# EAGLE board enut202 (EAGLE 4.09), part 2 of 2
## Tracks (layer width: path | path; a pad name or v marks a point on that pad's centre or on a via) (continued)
PD5  (via drill 0.4) (continued)
  Bottom 0.152: J5.60 14,72.18 14.05,72.13 12.3,70.38 12.3,62.07 13.06,61.31 17.56,61.31 v18.85,60.02 | v22.13,48.13 22.13,48.28 26.7,48.28 27.46,47.52 27.46,35.48 28.07,34.79 28.07,24.35 JP2.1
PD6  (via drill 0.4)
  Top 0.152: IC1.31 v18.03,59.57
  Bottom 0.152: J5.61 11.46,74.88 11.54,74.8 11.54,73.5 11.69,73.35 11.99,73.35 12.45,72.89 12.45,71.83 11.99,71.37 11.99,61.92 12.91,61.01 17.18,61.01 18.01,60.17 18.01,59.63 18.03,59.62 v18.03,59.57
PD7  (via drill 0.4)
  Top 0.152: IC1.32 v17.23,59.97
  Bottom 0.152: J5.62 11.69,72.13 11.69,61.77 12.75,60.7 16.57,60.7 17.25,60.02 17.25,59.94 v17.23,59.97
PE0  (via drill 0.4)
  Top 0.152: IC1.2 | IC1.2 | 31.2,48.36 31.21,48.37 IC1.2 | v38.36,70.07 38.36,73.86 J5.39 39.4,74.92 40.19,73.81 60.69,73.81 61.07,73.43 61.07,67.79 JP1.12 | v37.98,53.16 37.98,52.09 36.23,50.34 34.78,50.34 | IC1.2 31.25,48.36 32.26,48.36 32.34,48.28 32.72,48.28 34.78,50.34 | JP4.1C 18.32,23.13 19,22.45 22.66,22.45 24.19,23.97 24.19,29.46 27.77,29.46 29.67,31.36 29.67,32.74 30.36,33.42 v30.36,40.28 | 34.78,50.34 34.47,50.03 34.47,43.94 32.57,42.03 v32.03,42.03
  Bottom 0.152: v38.36,70.07 34.7,70.07 34.4,69.77 34.4,58.11 37.98,54.53 v37.98,53.16 | v30.36,40.28 v32.03,42.03
PE1  (via drill 0.4)
  Top 0.152: 31.23,49.16 31.2,49.12 | 31.23,49.16 IC1.3 | 31.23,49.16 31.25,49.17 31.25,49.27 31.32,49.2 32.95,49.2 34.4,50.64 36,50.64 37.37,52.02 v37.37,52.4 37.37,54.07 42.25,54.07 43.01,53.31 46.21,53.31 46.97,52.55 47.66,52.55 49.03,53.92 61.3,53.92 61.9,54.53 61.9,55.14 61.3,55.75 61.3,57.2 61.29,57.2 JP1.2 | JP4.9C 17.65,39.29 14.96,39.29 12.68,41.57 12.68,46.3 11.76,47.21 11.76,62.07 13.21,63.52 13.21,70.07 14.43,71.29 19.84,71.29 20.38,71.83 20.38,73.05 20.91,73.58 27.23,73.58 27.92,74.27 v27.92,75.48
  Bottom 0.152: v37.37,52.4 37.37,54.68 34.09,57.96 34.09,70 34.47,70.38 37.44,70.38 39.43,72.36 J5.40 39.04,73.05 38.36,73.73 38.36,74.88 37.29,75.94 28.38,75.94 v27.92,75.48
PE2  (via drill 0.4)
  Top 0.152: J5.41 36.84,74.8 36.84,74.88 38.59,76.02 62.82,76.02 63.28,75.56 63.28,69.08 v62.29,68.09 | IC1.4 31.23,49.96 32.95,49.96 33.94,50.95 35.69,50.95 36.76,52.02 v36.76,53.16
  Bottom 0.152: v36.76,53.16 36.76,54.83 33.79,57.81 33.79,70.23 34.24,70.68 36.76,70.68 38.13,72.05 38.13,73.12 36.86,74.39 J5.41 | v62.29,68.09 62.29,62.23 JP1.6
PE3  (via drill 0.4)
  Top 0.152: IC1.5 | IC1.5 | IC1.5 31.23,50.72 31.39,50.87 32.95,50.87 33.33,51.25 35.31,51.25 36.15,52.09 v36.15,52.4 | J5.42 36.86,72.87 35.69,74.04 35.69,75.33 36.68,76.32 63.28,76.32 63.73,75.86 63.73,68.17 64.11,67.79 64.11,66.8 63.66,66.34 62.36,66.34 62.36,64.82 61.68,64.13 61.68,64.05 | 61.68,64.05 59.47,64.05 59.24,64.28 R30.1 | 61.68,64.05 62.36,63.37 62.36,61.77 63.05,61.77 JP1.5
  Bottom 0.152: v36.15,52.4 36.15,54.99 33.48,57.65 33.48,70.45 34.02,70.99 35.54,70.99 36.86,72.31 J5.42
PE4  (via drill 0.4)
  Top 0.152: IC1.6 | IC1.6 | IC1.6 31.33,51.48 31.4,51.56 35.01,51.56 35.54,52.09 v35.54,53.16
  Bottom 0.152: v35.54,53.16 35.54,55.14 33.18,57.5 33.18,70.68 33.79,71.29 34.85,71.29 35.62,72.05 35.62,72.82 34.32,74.11 J5.43
PE5  (via drill 0.4)
  Top 0.152: IC1.7 | IC1.7 | IC2.29 47.61,23.74 v45.75,23.74 45.45,23.9 36,23.9 34.62,25.27 33.63,25.27 33.25,25.65 33.25,29.54 34.4,30.68 34.4,35.63 v35.01,36.24 | 31.23,52.36 31.27,52.32 | 31.23,52.36 IC1.7 | 31.23,52.36 31.2,52.4 29.75,52.4 29.75,47.37 30.28,46.83 30.28,45.61 v31.42,44.47 | IC1.7 31.26,52.4 v34.93,52.4
  Bottom 0.152: J5.44 32.87,70.91 32.87,57.35 34.93,55.29 v34.93,52.4 | v35.01,36.24 35.01,40.89 v31.42,44.47
PE6  (via drill 0.4)
  Top 0.152: IC1.8 | IC1.8 | v34.32,53.17 34.32,53.16 31.25,53.16 IC1.8
  Bottom 0.152: v34.32,53.17 34.32,53.08 34.32,55.44 32.57,57.2 32.57,71.37 33.02,71.83 33.02,72.82 31.78,74.06 J5.45
PE7  (via drill 0.4)
  Top 0.152: IC1.9 32.11,53.84 33.41,53.84 v33.44,53.82 | IC1.9 | J5.46 31.78,72.31 33.1,70.99 36.3,70.99 37.83,69.46 38.74,69.46 40.49,71.22 40.57,71.22 40.57,72.82 41.18,73.43 57.94,73.43 58.55,72.82 58.55,67.86 58.7,67.71 R31.1 58.7,66.8 58.17,66.8 58.17,64.13 58.78,63.37 60.69,63.37 JP1.8
  Bottom 0.152: v33.44,53.82 33.61,53.97 33.63,54 33.63,55.6 32.26,56.97 32.26,71.88 J5.46
PEN\
  Top 0.152: 33.39,47.52 33.41,47.52 | 33.39,47.52 R4.1 | IC1.1 31.29,47.52 33.39,47.52
PF0  (via drill 0.4)
  Top 0.152: IC1.61 v26.83,47.17
  Bottom 0.152: 26.59,46.95 24.49,44.85 20.22,44.85 | 26.59,46.95 26.85,47.21 | 20.22,44.85 20.25,44.85 | v26.83,47.17 26.62,46.91 26.59,46.95 | J6.5 8.11,49.5 8.26,49.35 8.26,45.84 9.25,44.85 20.22,44.85
PF1  (via drill 0.4)
  Top 0.152: IC1.60 | IC1.60 | IC1.60 26.01,45.59 v26.01,47.67
  Bottom 0.152: 26.03,47.57 26.01,47.29 v26.01,47.67 25.86,47.37 25.86,46.83 24.11,45.16 9.48,45.16 8.56,46.07 8.56,51.63 8.16,52.04 J6.7
PF2  (via drill 0.4)
  Top 0.152: IC1.59 25.23,45.67 v25.23,47.21
  Bottom 0.152: 25.02,46.98 23.5,45.46 9.78,45.46 8.87,46.38 8.87,53.92 8.21,54.58 J6.9 | 25.02,46.98 25.25,47.21 | 25.02,46.98 v25.23,47.21
PF3  (via drill 0.4)
  Top 0.152: IC1.58 24.43,45.67 v24.43,47.61
  Bottom 0.152: 20.22,45.77 20.23,45.77 | 20.22,45.77 23.2,45.77 24.41,46.98 24.41,47.59 v24.43,47.61 | J6.11 8.18,57.12 9.17,56.13 9.17,46.68 10.09,45.77 20.22,45.77
PF4  (via drill 0.4)
  Top 0.152: 23.63,45.47 | 23.63,45.47 IC1.57 23.65,45.59 23.65,47.21 | 23.65,47.21 23.65,47.19 v23.63,47.17 | IC3.11 41.49,57.97 41.41,57.88 40.65,57.88 39.81,57.04 39.81,55.29 39.04,54.53 v32.8,54.53 | 23.63,45.47 23.65,45.46 v23.65,43.02 | 23.65,47.21 23.65,47.98 24.03,48.36 26.78,48.36 27.23,48.81 v27.23,53.92
  Bottom 0.152: 23.39,46.95 22.51,46.07 10.39,46.07 9.48,46.98 9.48,58.34 8.16,59.66 J6.13 | 23.39,46.95 23.65,47.21 | v23.63,47.17 23.42,46.91 23.39,46.95 | v27.23,53.92 27.54,53.62 31.88,53.62 v32.8,54.53 | JP4.1A 22.59,24.45 22.59,31.67 22.89,31.97 22.89,42.57 v23.65,43.02
PF5  (via drill 0.4)
  Top 0.152: IC3.10 41.5,58.8 40.72,58.8 39.43,57.5 39.43,55.82 39.04,55.44 v32.8,55.44 | v22.89,43.71 22.89,45.52 IC1.56 22.83,45.67 v22.83,47.57 v22.83,47.58 22.81,47.59 22.89,47.67 22.89,47.9 23.8,48.81 25.94,48.81 26.47,49.35 v26.47,54.76
  Bottom 0.152: 22.81,47.29 22.81,47.59 | 22.81,47.29 22.81,47.06 22.13,46.38 10.7,46.38 9.78,47.29 9.78,60.55 8.13,62.2 J6.15 | v22.83,47.57 22.81,47.29 | v26.47,54.76 27.77,54.76 28.61,53.92 31.27,53.92 v32.8,55.44 | v22.89,43.71 22.59,43.71 22.59,32.28 21.75,31.44 21.75,31.36 21.72,31.36 JP4.5A
PF6  (via drill 0.4)
  Top 0.152: v22.03,47.13 IC1.55 22.13,44.62 22.13,43.1 22.89,42.34 24.72,42.34 v26.09,40.97
  Bottom 0.152: 22.05,47.13 22.05,47.14 | 22.05,47.13 v22.03,47.13 | 22.05,47.13 21.6,46.68 11,46.68 10.09,47.59 10.09,62.76 8.11,64.74 J6.17 | JP5.5 27.07,39.99 v26.09,40.97
PF7  (via drill 0.4)
  Top 0.152: IC1.54 | IC1.54 21.23,43.38 v23.5,41.12 | IC1.54 v21.23,47.61
  Bottom 0.152: v21.23,47.61 21.23,47.53 20.68,46.98 11.23,46.98 10.39,47.82 10.39,63.27 J6.19 | v23.5,41.12 23.2,40.81 23.2,31.97 24.81,30.36 JP5.2
POE+
  Bottom 0.61: J1.8 81.95,19.63 | JP3.3 81.95,20.65 J1.8 | J1.7 84.46,18.38 84.46,19.65 J1.8
POE-
  Bottom 0.61: JP3.2 75.23,17.04 80.04,17.04 80.04,14.6 81.95,14.6 J1.4 81.95,15.82 84.48,15.82 J1.5
RAMSEL\  (via drill 0.4)
  Top 0.152: v47.58,44.47 47.58,41.57 49.18,39.98 52.68,39.98 | 52.68,39.98 | 52.68,39.98 IC4.22 | IC3.6 41.58,61.92 43.31,61.92 43.92,62.53 v48.19,62.53
  Bottom 0.152: v47.58,44.47 49.18,46.15 49.18,50.49 48.49,51.18 48.49,51.79 49.41,52.7 49.41,56.21 49.71,56.51 49.71,61.69 48.87,62.53 v48.19,62.53
RD\  (via drill 0.4)
  Top 0.152: v46.28,24.58 46.89,24.58 IC2.31 | v51.24,28.62 51.24,31.82 53.06,31.82 53.83,32.58 53.83,42.26 53.45,42.26 IC4.24 53.45,42.79 v54.74,42.79 | IC1.34 15.21,58.8 v12.83,58.8 | IC3.3 42.47,64.37 43.16,63.67 48.04,63.67 48.95,62.76 48.95,61.16 48.57,60.78 48.42,60.78 48.19,60.55 48.19,59.94 48.65,59.48 49.33,59.48 51.47,57.35 52,57.35 54.82,54.53 v59.77,54.53
  Supply 0.305: J5.13 72.42,75.26 71.35,76.32 10.85,76.32 10.24,75.71 v10.24,73.81
  Bottom 0.152: v46.28,24.58 46.28,24.66 50.25,28.62 v51.24,28.62 | v10.24,73.81 10.24,71.83 11.38,70.68 11.38,60.24 v12.83,58.8 | v54.74,42.79 55.2,43.25 55.2,53 56.72,54.53 v59.77,54.53 60.69,55.44 62.21,55.44 62.67,54.99 67.54,54.99 68.23,55.67 68.23,63.98 73.94,69.69 73.94,72.97 72.42,74.49 J5.13
RDYRTN\  (via drill 0.4)
  Top 0.152: IC2.46 | IC2.46 | RN1.5 42.32,28.94 v42.32,28.24 | IC2.46 41.03,26.48 41.03,26.49 v41.03,24.73
  Bottom 0.152: v42.32,28.24 42.32,26.03 v41.03,24.73
RE485\
  Top 0.152: IC7.2 27.01,14.6 28.07,14.6 28.68,15.21 28.68,17.04 27.77,17.95 27.77,20.92 26.09,22.6 26.09,24.39 JP2.3 26.85,25.95 26.85,26.79 JP2.5
RESET  (via drill 0.4)
  Top 0.152: IC6.1 67.3,56.13 v64.65,56.13 | 37.52,32.67 37.52,32.66 | IC5.8 37.52,32.67 | 37.52,32.67 37.52,32.74 52.46,32.74 v52.76,32.43 | v59.92,57.04 59.92,61.08 59.24,61.77 R29.1
  Bottom 0.152: v64.65,56.13 64.57,56.28 59.92,56.28 | 59.92,56.28 v59.92,57.04 | 59.92,56.28 57.26,56.28 53.68,52.7 53.68,33.35 v52.76,32.43
RESET\  (via drill 0.4)
  Top 0.152: IC5.9 37.48,33.95 v35.23,33.95 | 67.39,65.74 IC6.18 67.34,65.81 | R2.1 31.12,66.43 31.12,65.58 | 31.12,65.58 D1.A | 31.12,65.58 28.91,63.37 28.22,63.37 27.77,62.91 27.46,62.91 26.83,62.28 IC1.20 26.85,61.56 v26.85,59.86 28.68,58.03 28.68,47.29 v28.61,47.21 | v28.99,34.26 28.07,33.42 21.78,33.42 JP4.6A 21.22,33.35 20.15,32.28 18.62,32.28 17.71,31.36 JP4.5C | J5.9 77.4,74.9 76.31,73.81 76.31,71.75 75.7,71.14 68.76,71.14 68.42,70.8 C22.1 67.97,69.82 66.48,68.32 66.48,65.81 67.34,65.81 | S1.2 18.16,8.2 v20.15,8.2 27.62,8.2 S1.1 | 67.34,65.81 67.39,65.81
  Bottom 0.152: v26.85,59.86 26.09,59.86 25.63,59.41 24.19,59.41 20.38,63.14 14.28,63.14 14.13,63.29 14.13,68.63 15.35,69.84 18.7,69.84 20.38,71.52 20.38,76.47 20.53,76.63 48.8,76.63 49.41,75.94 72.95,75.94 73.49,75.41 73.49,74.65 74.4,73.73 76.38,73.73 77.53,74.88 J5.9 | v35.23,33.95 29.29,33.95 v28.99,34.26 28.99,35.17 28.61,35.55 v28.61,47.21 | JP4.6A 20.76,32.4 20.76,21.61 20.15,21 v20.15,8.2
RO  (via drill 0.4)
  Top 0.152: IC7.1 27.01,13.31 v27.01,12.47
  Bottom 0.152: JP1.10 59.09,63.02 59.09,59.71 52.76,53.39 52.76,39.37 51.24,37.84 51.24,32.51 46.44,27.71 46.44,26.49 44.38,24.43 44.38,13.61 43.23,12.47 v27.01,12.47
RRCUP
  Top 0.152: R13.2 54.82,17.95 54.82,16.28 R12.2 54.82,15.36 54.82,12.54 C13.2
RS485A
  Top 0.152: J4.2 | JP6.6 10.62,15.21 J4.2 | IC7.6 22.05,16.12 22.31,16.38 22.31,19.07 21.26,19.07 20.4,19.93 20.35,19.97 12.57,19.97 11.3,18.7 11.28,18.64 JP6.10
  Bottom 0.152: JP6.6 10.19,15.64 10.19,17.11 11.3,18.23 11.3,18.54 11.29,18.54 JP6.10
RS485B
  Top 0.152: IC7.7 20.51,14.58 R24.1 19.08,15.85 17.81,17.11 15.27,17.11 14.63,16.48 14.63,16 14.16,15.53 12.25,15.53 11.25,16.53 JP6.8 10.08,17.75 J4.1 | J4.1
RSHIELD  (via drill 0.4)
  Top 0.152: J3.G1 88.44,66.33 83.85,66.33 C25.2 83.72,66.33 v82.58,66.33 81.31,66.33 C24.2 | C27.2 83.85,56.8 v82.58,56.8 81.44,56.8 C26.2
  Bottom 0.152: J3.G1 90.2,64.56 90.2,59.66 91.47,58.39 91.47,43.47 88.93,40.93 88.91,40.86 J3.G2 | v82.58,66.33 v82.58,56.8
  Bottom 0.61: J3.G2 87.66,42.06 R32.2
RXD  (via drill 0.4)
  Top 0.152: v64.11,64.21 72.72,64.21 73.41,64.89 IC6.13
  Bottom 0.152: v64.11,64.21 64.11,66.03 63.51,66.64 JP1.11
SA14  (via drill 0.4)
  Top 0.152: IC4.3 39.48,50.13 39.27,50.34 39.27,52.24 39.43,52.4 v39.43,52.78 | IC3.36 49.63,67.64 49.64,67.64 49.64,66.72 49.41,66.49 45.9,66.49 44.15,64.74 43.31,64.74 42.85,65.2 42.85,66.42 42.4,66.87 v39.96,66.87
  Bottom 0.152: v39.43,52.78 39.43,54.07 40.19,55.21 40.19,59.94 39.27,60.85 39.27,66.19 v39.96,66.87
SA15  (via drill 0.4)
  Top 0.152: IC3.34 51.23,67.02 v49.41,65.2 | IC4.31 | v49.18,51.41 IC4.31
  Bottom 0.152: v49.41,65.2 49.41,62.84 50.02,62.23 50.02,56.21 49.71,55.9 49.71,51.94 v49.18,51.41
SA16  (via drill 0.4)
  Top 0.152: v42.93,54.91 43.23,55.52 IC3.12 | v43.01,51.41 42.02,51.41 IC4.2
  Bottom 0.152: v43.01,51.41 43.01,51.48 43.31,51.79 43.31,53.16 42.63,53.84 42.63,54.3 42.93,54.6 v42.93,54.91
SA17  (via drill 0.4)
  Top 0.152: IC3.8 41.58,60.32 42.7,60.32 43.84,61.46 v48.27,61.46 | IC4.30 52.76,50.11 | IC4.30 | v48.19,50.19 52.68,50.19 IC4.30
  Bottom 0.152: v48.19,50.19 48.19,51.94 49.1,52.85 49.1,56.36 49.41,56.66 49.41,61.23 49.18,61.46 v48.27,61.46
SA18  (via drill 0.4)
  Top 0.152: v39.96,61.16 40.8,61.16 IC3.7 | v40.04,53.46 40.57,52.93 IC4.1
  Bottom 0.152: v40.04,53.46 39.96,53.92 40.04,54 40.49,54.53 40.49,60.62 v39.96,61.16
TDI  (via drill 0.4)
  Top 0.152: v23.96,32.2 24.64,31.52 25.86,31.52 26.47,30.91 JP5.1 | v23.96,35.33 23.96,38.76 21.9,38.76 JP4.9A
  Bottom 0.152: v23.96,32.2 23.88,32.28 23.88,35.25 v23.96,35.33
TDO  (via drill 0.4)
  Top 0.152: v23.5,27.78 22.43,27.78 22.28,27.63 JP4.3A
  Bottom 0.152: v23.5,27.78 25.18,29.46 25.94,29.46 25.94,33.19 25.33,33.8 JP5.6
TDOX
  Top 0.152: JP4.3B 19.49,27.36 18.62,26.49 14.15,26.49 J7.3
TPI+  (via drill 0.4)
  Top 0.152: 56.8,15.9 R12.1 | R11.1 56.85,15.85 56.8,15.9 | IC2.17 49.03,18.97 v49.03,19.17 | 56.8,15.9 56.72,15.97 v56.72,17.04
  Bottom 0.152: v56.72,17.04 56.42,17.34 51.54,17.34 49.71,19.17 v49.03,19.17 49.03,18.97
TPI-  (via drill 0.4)
  Top 0.152: 56.8,18.41 56.77,18.38 R13.1 | R10.1 56.82,18.38 56.8,18.41 | IC2.18 47.59,19.4 v46.21,19.4 | 56.8,18.41 56.72,18.41 v56.72,19.48
  Bottom 0.152: v56.72,19.48 56.34,19.86 46.66,19.86 v46.21,19.4
TPO+  (via drill 0.4)
  Top 0.152: TR1.16 61.14,9.5 60.15,8.5 v58.55,8.5 58.23,8.82 R20.1 | IC2.14 46.25,17.77 v46.21,17.72
  Bottom 0.152: v58.55,8.5 49.03,8.5 46.21,11.32 v46.21,17.72
TPO-  (via drill 0.4)
  Top 0.152: TR1.14 62.36,12.01 62.34,12.04 R15.1 59.92,12.05 v59.92,13.23 | 47.62,18.18 IC2.15 48.89,18.17 v49.1,17.95
  Bottom 0.152: v59.92,13.23 59.92,13.99 57.79,16.12 52.15,16.12 50.32,17.95 v49.1,17.95
TXD  (via drill 0.4)
  Top 0.152: v74.1,64.28 74.71,64.89 IC6.12 | v72.19,62.38 67.54,57.73 63.81,57.73 JP1.1
  Bottom 0.152: v72.19,62.38 v74.1,64.28
VCC3  (via drill 0.4)
  Top 0.152: R28.2 74.01,5.29 74.02,5.3 73.26,6.07 64.65,6.07 64.65,21.15 v59.92,21.15
  Top 0.305: 53,60.3 IC3.26 52.98,60.32 54.59,60.32 55.07,60.8 C41.1
  Top 0.406: 66.07,37.75 66.08,37.75 66.09,37.77 v68.46,37.77 | 62.16,42.57 62.21,42.57 | C36.+ 62.16,42.57 | v62.13,43.86 62.13,42.57 62.16,42.57 | FB3.1 53.3,29.84 v54.89,29.84 | FB4.2 58.44,21.15 v59.92,21.15 | v61.19,54.81 59.82,55.8 58.51,55.8 FB5.2 58.35,55.96 58.35,60.12 57.74,60.73 55.67,60.73 C41.1
  Top 0.61: C35.1 66.07,37.75 IC9.3 63.85,38.18 63.85,40.61 v62.26,40.61 62.26,42.52 C36.+
  Bottom 0.152: J5.2 87.51,71.67 87.66,71.67
  Bottom 0.406: J5.1 J5.2 87.66,71.67 87.66,70.53 78.52,70.53 78.52,64.13 73.33,58.95 73.33,43.94 68.53,39.14 68.53,37.84 v68.46,37.77 | v62.26,40.61 62.29,40.59 62.21,40.51 62.21,29.84 v54.89,29.84 54.89,27.25 59.92,22.22 v59.92,21.15 | v62.13,43.86 62.13,53.49 v61.19,54.81
VCC3N  (via drill 0.4)
  Top 0.152: IC2.86 32.43,16.66 | 32.43,16.66 IC2.85 | 32.43,16.66 32.41,16.66 32.41,16.58 v30.82,16.58 | IC2.77 30.45,20.16 C9.1 | IC2.110 39.04,11.16 39.04,9.27 38.09,9.27 C15.1 | IC2.62 34.62,28.09 C6.1 | IC2.1 47.66,12.54 49.94,12.54 49.94,12.35 | IC2.44 41.79,26.37 41.79,27.48 39.43,27.48 39.43,28.99 C7.1 | IC2.120 43.03,10.28 42.55,9.8 42.55,9.65 42.13,9.23 C16.1 | IC2.98 34.24,11.17 34.24,7.59 C14.1 34.32,7.59 34.32,5.68 | v34.24,4.39 34.32,4.39 34.32,5.68 | 34.32,5.68 R19.1 | 49.94,12.35 49.94,12.31 | 49.94,12.35 C12.1 | IC2.33 46.21,27.1 46.21,28.85 C8.1 45.6,29.76 44.84,30.53 RN1.1 44.76,31.97 43.92,31.97 | 38.13,29.31 38.13,29.84 38.44,30.14 41.79,30.14 42.31,30.67 RN1.4 42.25,31.01 42.25,31.97 43.08,31.97 | 43.08,31.97 43.92,31.97 | RN1.3 43.08,30.95 43.08,31.97 | RN1.2 43.92,31.97
  Top 0.305: C15.1 37.98,9.18 v37.98,8.05 | C16.1 42.09,9.18 v42.09,8.05 | C7.1 38.13,29.31 38.05,29.38 v38.05,29.31 34.85,29.31 34.85,28.23 C6.1
  Top 0.406: v29.96,19.34 C9.1 | R7.1 29.29,13.84 29.29,14.98 v29.9,14.98 | FB3.2 48.95,29.87 v48.95,29.31 | v50.02,11.1 C12.1
  Supply 0.406: 43.08,13.53 45.52,11.1 v50.02,11.1
  pour Supply (isolate 0.305, no thermals): 29.88,30.45 53.37,30.45 53.37,24.1 43.21,24.1 43.21,1.24 29.88,1.24
VCC3X  (via drill 0.4)
  Top 0.152: IC3.15 | IC3.15 | IC3.15 | IC3.35
  Top 0.305: IC3.15 45.65,56.28 45.67,56.28 45.67,54.2 C39.1 45.63,54.15 43.92,54.15 v43.31,54.07
  Top 0.406: IC3.35 50.4,67.64 50.4,68.5 C40.1 49.66,69.82 v48.95,70.53 | FB5.1 55.25,55.86 55.25,55.9 54.26,55.9 v54.26,56.94
  pour Supply (isolate 0.305, rank 3): 39.4,71.72 63.85,71.72 63.85,49.5 39.4,49.5
VCC5  (via drill 0.4)
  Top 0.152: R25.2 20.02,13.03 20.55,13.03 IC7.8
  Top 0.406: IC7.8 22.57,13.31 23.34,12.54 23.34,10.79 23.37,10.77 | 23.37,10.77 v23.37,9.34 | 23.37,10.77 C32.1 | 37.81,41.88 | 37.81,41.88 C37.1 | IC5.14 37.5,41.56 37.81,41.88 | IC8.2 68,42.79 67.16,43.63 66.09,43.63 66.09,43.62 C34.1 66.02,43.6 66.02,43.56 64.65,43.56 64.65,48.23 | 64.65,48.23 C20.+ | 37.81,41.96 37.75,41.96 | 37.81,41.88 37.81,41.96 | 37.81,41.96 37.83,41.96 | FB1.1 35.89,45.77 37.33,45.77 v37.33,46.83 | FB6.2 64.65,52.61 64.65,48.89 | 64.65,48.23 64.65,48.89 | 37.81,41.96 37.81,43.25 v39.5,43.25 | FB7.2 66.35,48.89 64.65,48.89 | IC9.1 v65.49,33.27
  Top 0.61: IC8.2 73.06,42.52 | v11.48,40.46 11.46,40.48 FB2.1
  Supply 0.152: 28.61,5.38 28.83,5.38
  other vias: 76.86,35.53 83.22,35.53 77.5,49.5 78.77,49.5 80.04,49.5 81.31,49.5 82.58,49.5 83.85,49.5 85.12,49.5
  pour Supply (isolate 0.305, rank 2): 73.69,77.44 97.19,77.44 97.19,24.1 54.64,24.1 54.64,31.72 28.61,31.72 28.61,1.24 0.67,1.24 0.67,40.93 33.05,40.93 33.05,48.23 73.69,48.23
  pour Top (isolate 0.203, rank 3, no thermals): 72.42,49.5 96.55,49.5 96.55,35.53 72.42,35.53
VCC5P  (via drill 0.4)
  Top 0.152: R2.2 31.14,68.93 33.69,68.93 D1.C 33.69,69.31 v35.39,69.31
  Top 0.305: IC1.21 26.01,61.57 26.01,62.91 26.85,62.91 27.52,63.58 C3.1 27.54,64.12 27.54,64.13 28.22,64.13 v28.68,64.59 | C4.1 18.57,43.53 18.55,43.56 19.63,44.64 IC1.52
  Top 0.406: FB1.2 35.89,49.04 37.18,49.04 v37.18,49.18 | v31.42,45.77 31.88,45.77 32.44,45.79 R4.2
  Top 0.61: 18.55,43.56 18.47,43.48 17.86,43.48 v17.25,44.09
  Supply 0.61: v17.25,44.09 17.25,46.45 13.59,46.45 v13.59,47.59 13.59,47.67
  pour Supply (isolate 0.305): 7.02,71.72 38.13,71.72 38.13,49.5 31.78,49.5 31.78,42.2 27.97,42.2 27.97,46.32 12.73,46.32 12.73,64.11 7.02,69.82
VCC5R
  Top 0.406: FB6.1 58.54,52.85 54.65,52.85 C38.1 54.48,52.7 52.76,52.7 IC4.32
VCC5S  (via drill 0.4)
  Top 0.305: IC6.17 68.61,67.73 C23.1 68.42,67.86 v67.24,67.86
  Top 0.406: FB7.1 69.52,48.92 v69.52,50.41 68,50.41 68,51.85 C28.1
  pour Supply (isolate 0.305, rank 3, no thermals): 65.12,71.72 72.42,71.72 72.42,49.5 65.12,49.5
WR\  (via drill 0.4)
  Top 0.152: IC1.33 15.21,59.57 15.19,59.56 v13.52,59.56 | IC3.5 40.35,62.77 v39.96,62.38 | IC2.32 v52.15,24.97 v52.15,24.96 | IC4.29 52.79,48.81 v54.44,48.81
  Supply 0.305: J5.14 72.42,72.66 71.51,73.58 40.72,73.58 | v39.96,62.38 39.5,62.38 39.04,62.84 39.04,69.08 40.72,70.76 40.72,73.58 | v13.52,59.56 12.68,60.4 12.68,72.89 13.37,73.58 40.72,73.58
  Bottom 0.152: v52.15,24.96 52.15,30.98 53.98,32.81 53.98,48.36 v54.44,48.81 53.98,49.27 53.98,52.4 57.03,55.52 57.33,55.82 63.96,55.82 64.34,55.44 65.03,55.44 65.41,55.82 65.41,67.64 68.31,70.53 70.97,70.53 72.42,71.98 J5.14
XTDI  (via drill 0.4)
  Top 0.152: IC3.9 41.52,59.56 40.72,59.56 38.74,57.58 v38.74,56.13 | v38.59,52.4 38.44,51.94 36.53,50.03 35.16,50.03 34.85,49.73 34.85,43.78 32.34,41.27 29.75,41.27 29.44,40.97 29.44,39.67 29.75,39.37 29.75,33.88 28.22,32.35 JP5.3
  Bottom 0.152: v38.74,56.13 38.59,55.82 v38.59,52.4
XTDO  (via drill 0.4)
  Top 0.152: 53.06,58.72 52.99,58.8 52.96,58.77 IC3.24 52.91,58.78 52.91,58.8 51.54,58.8 50.25,60.17 v48.8,60.17 | v48.27,47.06 47.2,47.06 46.59,47.67 45.9,47.67 43.84,45.61 38.28,45.61 36.07,43.4 35.01,43.4 32.57,40.97 30.05,40.97 29.75,40.66 29.75,39.9 30.05,39.59 30.05,33.65 29.37,32.96 29.37,32.05 28.68,31.36 26.55,31.36 25.56,32.35 JP5.4
  Bottom 0.152: v48.8,60.17 48.8,53.08 47.88,52.17 47.88,50.87 47.58,50.57 47.58,49.88 48.27,49.2 v48.27,47.06

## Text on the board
Bottom: Ethernut 2.0 Rev-A
tNames: PD | PB | PE | AB | DB | Misc | GND | PWR | CPLD | 232 | www.egnite.de | It's better | to burn out | than fade | away | RS 232 | SRAM | 5V | NEG | ISP | JTAG | 3.3V | 9V | ISP/JTAG | B | A | ETHER | 485 | S | P | RS 485 | 100BaseT | Transformer | Activity | Link | Power | Reset
Measures: 11.4 | 18.0 | 8.9 | 10.4 | 3.8 | 4.0 | 4.4 | 4.4 | 5.6 | 10.7 | 10.7 | 13.9 | 78.0 | 30.5 | 22.8 | d=3.0 | 15.2 | 3.8 | 3.8 | 3.8 | 15.2 | 7.1 | 4.0 | 98.0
